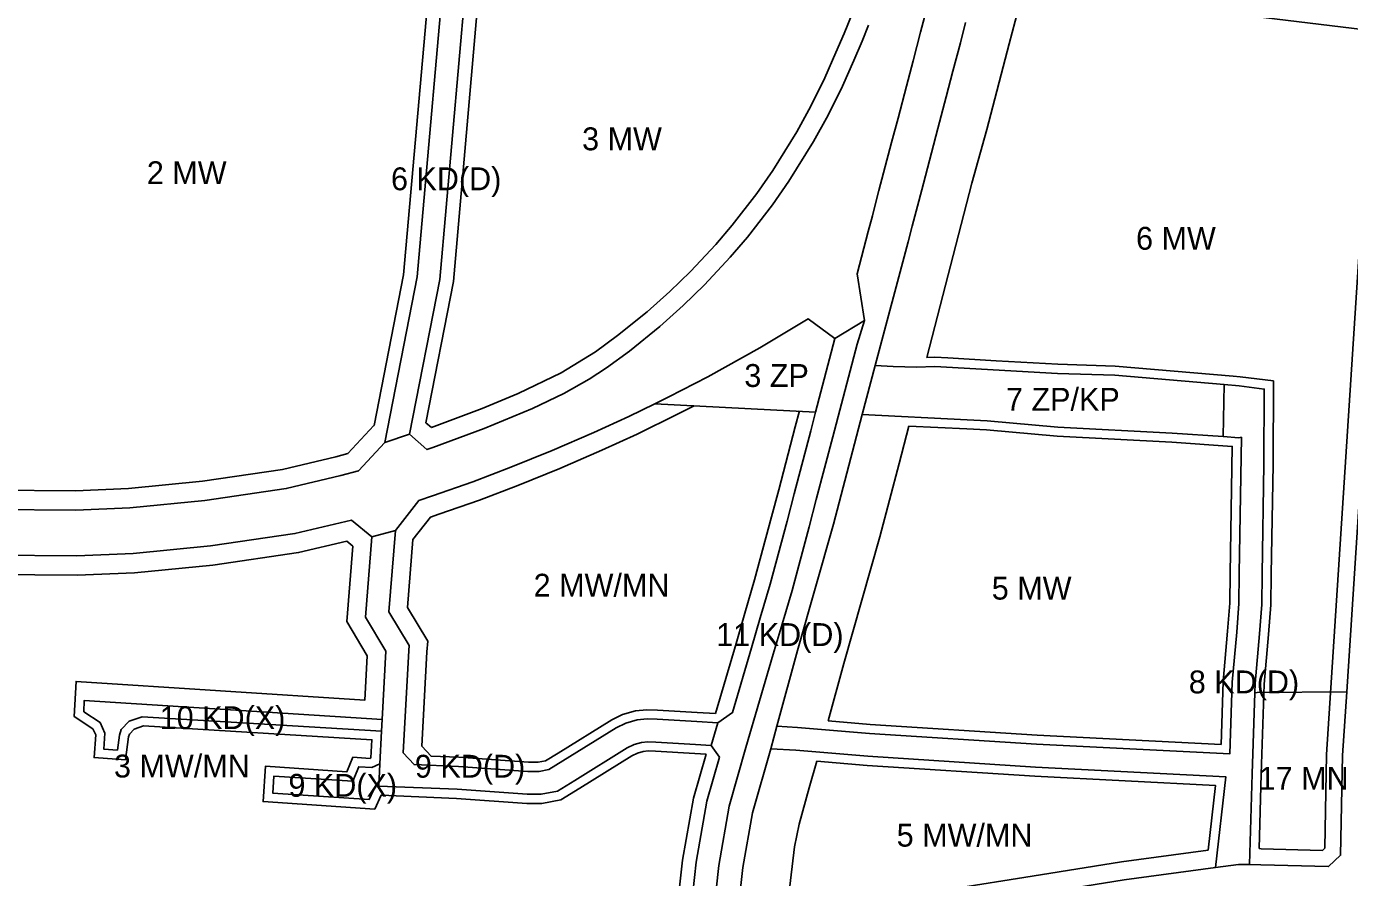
# Model space of a CAD drawing. Extents: x 7424258 to 7426021, y 5551671 to 5553193.
# Drawn here: x 7425011 to 7425590, y 5551891 to 5552263 of the extents above; entities that cross this region are included whole.
import ezdxf

# ---------------------------------------------------------------- set-up
doc = ezdxf.new("R2010")
doc.units = 0
for name, color, linetype in [('linie_rozgraniczajace', 7, 'Continuous'), ('linie_zabudowy_nieprzekraczalne', 7, 'Continuous'), ('oznaczenia_przeznaczen', 7, 'Continuous')]:
    doc.layers.add(name, color=color, linetype=linetype)

msp = doc.modelspace()

# ---------------------------------------------------------------- linework, layer by layer
at = {"layer": 'linie_rozgraniczajace'}
for points in [[(7424997.27, 5552325.91), (7425012.96, 5552360.1), (7425019.81, 5552362.55), (7425024.68, 5552360.58), (7425067.84, 5552343.87), (7425123.64, 5552327.99), (7425149.52, 5552322.73), (7425176.9, 5552317.94), (7425191.14, 5552316.45), (7425195.65, 5552310.79), (7425181.78, 5552153.52), (7425167.65, 5552081.05), (7425156.08, 5552068.62), (7425148.38, 5552066.54), (7425124.54, 5552060.86), (7425088.94, 5552055.71), (7425056.14, 5552052.4), (7425032.48, 5552051.43), (7424996.02, 5552051.74)], [(7425379.37, 5552263.62), (7425376.51, 5552256.56), (7425372.87, 5552248.13), (7425367.91, 5552236.88), (7425361.63, 5552224.15), (7425355.3, 5552212.64), (7425344.54, 5552195.31), (7425337.27, 5552184.92), (7425326.31, 5552170.76), (7425318.86, 5552162.02), (7425307.54, 5552149.92), (7425298.23, 5552140.87), (7425287.97, 5552131.72), (7425274.71, 5552121.02), (7425264.69, 5552113.7), (7425257.13, 5552108.73), (7425245.98, 5552102.38), (7425232.26, 5552095.88), (7425211.16, 5552087.11), (7425188.68, 5552078.8), (7425186.11, 5552077.95), (7425178.53, 5552084.62), (7425191.71, 5552152.38), (7425205.62, 5552309.91)], [(7425404.45, 5552269.24), (7425402.13, 5552260.45), (7425398.85, 5552247.95), (7425395.93, 5552236.83), (7425392.27, 5552222.89), (7425389.47, 5552212.23), (7425385.96, 5552198.95), (7425383.93, 5552191.17), (7425382.76, 5552186.71), (7425381.04, 5552180.19), (7425379.23, 5552173.31), (7425374.35, 5552154.75), (7425377.61, 5552134.39), (7425364.66, 5552126.55), (7425352.92, 5552135.1), (7425350.78, 5552133.84), (7425331.76, 5552122.47), (7425309.05, 5552109.69), (7425292.01, 5552100.99), (7425285.84, 5552097.94), (7425274.48, 5552092.35), (7425259.12, 5552085.41)], [(7425310.41, 5551865.34), (7425313.81, 5551896), (7425318.39, 5551921.94), (7425325.72, 5551947.69), (7425337.66, 5551988.37), (7425341.53, 5552001.56), (7425345.87, 5552016.33), (7425353.33, 5552044.09), (7425356.47, 5552056.06), (7425363.7, 5552083.52), (7425374.33, 5552124.01), (7425377.61, 5552134.39), (7425374.35, 5552154.75), (7425379.23, 5552173.31), (7425381.04, 5552180.19), (7425382.76, 5552186.71), (7425383.93, 5552191.17), (7425385.96, 5552198.95), (7425389.47, 5552212.23), (7425392.27, 5552222.89), (7425395.93, 5552236.83), (7425398.85, 5552247.95), (7425402.13, 5552260.45), (7425404.45, 5552269.24)], [(7424996.02, 5552051.74), (7425032.48, 5552051.43), (7425056.14, 5552052.4), (7425088.94, 5552055.71), (7425124.54, 5552060.86), (7425148.38, 5552066.54), (7425156.08, 5552068.62), (7425167.65, 5552081.05), (7425178.53, 5552084.62), (7425186.11, 5552077.95), (7425188.68, 5552078.8), (7425211.16, 5552087.11), (7425232.26, 5552095.88), (7425245.98, 5552102.38), (7425257.13, 5552108.73), (7425264.69, 5552113.7), (7425274.71, 5552121.02), (7425287.97, 5552131.72), (7425298.23, 5552140.87), (7425307.54, 5552149.92), (7425318.86, 5552162.02), (7425326.31, 5552170.76), (7425337.27, 5552184.92), (7425344.54, 5552195.31), (7425355.3, 5552212.64), (7425361.63, 5552224.15), (7425367.91, 5552236.88), (7425372.87, 5552248.13), (7425376.51, 5552256.56), (7425379.37, 5552263.62)], [(7425421.85, 5552264.67), (7425419.54, 5552255.88), (7425416.26, 5552243.37), (7425413.33, 5552232.27), (7425409.68, 5552218.34), (7425406.88, 5552207.65), (7425403.37, 5552194.36), (7425401.34, 5552186.6), (7425400.16, 5552182.14), (7425398.44, 5552175.61), (7425396.64, 5552168.73), (7425382.23, 5552114.68), (7425376.58, 5552093.23), (7425363.97, 5552045.24), (7425348.26, 5551989.98), (7425339.27, 5551956.93), (7425336.58, 5551947.06), (7425328.59, 5551919.07), (7425324.39, 5551895.19), (7425320.85, 5551863.31), (7425320.24, 5551863.23), (7425309.95, 5551861.15), (7425310.41, 5551865.34)], [(7425607.51, 5552262.2), (7425588.61, 5551971.9), (7425549.49, 5551971.62), (7425548.39, 5551971.53), (7425548.52, 5551975.6), (7425550.44, 5551997.31), (7425551.41, 5552010.12), (7425551.58, 5552023.54), (7425552.36, 5552071.42), (7425552.52, 5552104.4), (7425541.56, 5552105.82), (7425534.93, 5552106.38), (7425487.07, 5552110.47), (7425462.01, 5552111.26), (7425408.31, 5552114.33), (7425400.38, 5552113.93), (7425390.12, 5552114.25), (7425382.23, 5552114.68), (7425396.64, 5552168.73), (7425398.44, 5552175.61), (7425400.16, 5552182.14), (7425401.34, 5552186.6), (7425403.37, 5552194.36), (7425406.88, 5552207.65), (7425409.68, 5552218.34), (7425413.33, 5552232.27), (7425416.26, 5552243.37), (7425419.54, 5552255.88), (7425421.85, 5552264.67)], [(7425491.27, 5551889.67), (7425531.19, 5551895.08), (7425541.24, 5551896.43), (7425546.12, 5551896.39), (7425551.01, 5551896.36), (7425580.68, 5551895.56), (7425585.95, 5551900.49), (7425586.81, 5551944.16), (7425588.61, 5551971.9), (7425607.51, 5552262.2)], [(7425300.21, 5551864), (7425303.91, 5551897.42), (7425308.63, 5551924.18), (7425314.13, 5551943.45), (7425310.5, 5551948.55), (7425313.39, 5551958.39), (7425319.78, 5551962.92), (7425328.07, 5551991.18), (7425331.94, 5552004.37), (7425336.24, 5552019.04), (7425343.67, 5552046.66), (7425346.8, 5552058.59), (7425354.03, 5552086.06), (7425356.18, 5552094.28), (7425364.66, 5552126.55), (7425377.61, 5552134.39), (7425374.33, 5552124.01), (7425363.7, 5552083.52), (7425356.47, 5552056.06), (7425353.33, 5552044.09), (7425345.87, 5552016.33), (7425341.53, 5552001.56), (7425337.66, 5551988.37), (7425325.72, 5551947.69), (7425318.39, 5551921.94), (7425313.81, 5551896), (7425310.41, 5551865.34)], [(7425259.12, 5552085.41), (7425240.92, 5552077.45), (7425222.83, 5552070.18), (7425206.17, 5552063.81), (7425188.53, 5552057.68), (7425182.56, 5552055.69), (7425172.27, 5552042.59), (7425162.01, 5552039.75), (7425153.15, 5552047.11), (7425128.3, 5552041.2), (7425091.38, 5552035.86), (7425057.55, 5552032.45), (7425032.81, 5552031.43), (7424995.89, 5552031.74)], [(7424995.89, 5552031.74), (7425032.81, 5552031.43), (7425057.55, 5552032.45), (7425091.38, 5552035.86), (7425128.3, 5552041.2), (7425153.15, 5552047.11), (7425162.01, 5552039.75), (7425159.22, 5552004.59), (7425168.1, 5551989.8), (7425166.49, 5551959.88), (7425036.13, 5551968.24), (7425035.88, 5551963.25), (7425043.08, 5551958.49), (7425045.19, 5551953.93), (7425044.69, 5551946.94), (7425050.67, 5551946.51), (7425051.6, 5551953.07), (7425052.32, 5551955.53), (7425055.76, 5551959.08), (7425061.41, 5551961.09), (7425166.24, 5551954.79), (7425165.48, 5551940.52), (7425162.02, 5551938.82), (7425156.28, 5551939.19), (7425153.62, 5551932.84), (7425119.13, 5551935.13), (7425118.63, 5551927.65), (7425160.77, 5551924.81), (7425163.51, 5551930.86), (7425164.97, 5551930.75), (7425199.3, 5551929.35), (7425229.93, 5551927.18), (7425236.07, 5551927.14), (7425243.17, 5551928.5), (7425250.84, 5551933.23), (7425273.78, 5551947.42), (7425276.85, 5551948.95), (7425279.93, 5551949.84), (7425282.73, 5551950.09), (7425286.33, 5551949.98), (7425303.58, 5551948.94), (7425310.5, 5551948.55), (7425314.13, 5551943.45), (7425308.63, 5551924.18), (7425303.91, 5551897.42), (7425300.21, 5551864)]]:
    msp.add_lwpolyline(points, dxfattribs=at)
for points in [[(7425167.65, 5552081.05), (7425181.78, 5552153.52), (7425195.65, 5552310.79), (7425205.62, 5552309.91), (7425191.71, 5552152.38), (7425178.53, 5552084.62)], [(7425285.84, 5552097.94), (7425292.01, 5552100.99), (7425309.05, 5552109.69), (7425331.76, 5552122.47), (7425350.78, 5552133.84), (7425352.92, 5552135.1), (7425364.66, 5552126.55), (7425356.18, 5552094.28)], [(7425376.58, 5552093.23), (7425382.23, 5552114.68), (7425390.12, 5552114.25), (7425400.38, 5552113.93), (7425408.31, 5552114.33), (7425462.01, 5552111.26), (7425487.07, 5552110.47), (7425534.93, 5552106.38), (7425534.55, 5552083.59), (7425512.27, 5552085.09), (7425462.15, 5552087.72), (7425431.2, 5552090.54), (7425422.51, 5552090.96)], [(7425336.58, 5551947.06), (7425339.27, 5551956.93), (7425348.29, 5551956.43), (7425379.75, 5551953.75), (7425452.93, 5551949.03), (7425537.46, 5551944.78), (7425538.54, 5551976.22), (7425540.47, 5551998.13), (7425541.41, 5552010.57), (7425541.59, 5552023.69), (7425542.55, 5552083.28), (7425541.46, 5552083.12), (7425534.55, 5552083.59), (7425534.93, 5552106.38), (7425541.56, 5552105.82), (7425552.52, 5552104.4), (7425552.36, 5552071.42), (7425551.58, 5552023.54), (7425551.41, 5552010.12), (7425550.44, 5551997.31), (7425548.52, 5551975.6), (7425548.39, 5551971.53), (7425547.17, 5551936.1), (7425546.12, 5551896.39), (7425541.24, 5551896.43), (7425531.19, 5551895.08), (7425535.65, 5551934.86), (7425452.35, 5551939.05), (7425379, 5551943.78), (7425347.58, 5551946.45)], [(7425172.27, 5552042.59), (7425182.56, 5552055.69), (7425188.53, 5552057.68), (7425206.17, 5552063.81), (7425222.83, 5552070.18), (7425240.92, 5552077.45), (7425259.12, 5552085.41), (7425274.48, 5552092.35), (7425285.84, 5552097.94), (7425356.18, 5552094.28), (7425354.03, 5552086.06), (7425346.8, 5552058.59), (7425343.67, 5552046.66), (7425336.24, 5552019.04), (7425331.94, 5552004.37), (7425328.07, 5551991.18), (7425319.78, 5551962.92), (7425313.39, 5551958.39), (7425304.16, 5551958.92), (7425286.8, 5551959.97), (7425282.45, 5551960.11), (7425278.08, 5551959.71), (7425273.2, 5551958.3), (7425268.91, 5551956.16), (7425245.58, 5551941.74), (7425239.49, 5551937.98), (7425235.14, 5551937.14), (7425230.32, 5551937.17), (7425199.86, 5551939.34), (7425180.49, 5551940.13), (7425175.75, 5551945.32), (7425178.12, 5551989.98), (7425178.29, 5551992.23), (7425169.44, 5552006.99)], [(7425339.27, 5551956.93), (7425348.26, 5551989.98), (7425363.97, 5552045.24), (7425376.58, 5552093.23), (7425422.51, 5552090.96), (7425431.2, 5552090.54), (7425462.15, 5552087.72), (7425512.27, 5552085.09), (7425534.55, 5552083.59), (7425541.46, 5552083.12), (7425542.55, 5552083.28), (7425541.59, 5552023.69), (7425541.41, 5552010.57), (7425540.47, 5551998.13), (7425538.54, 5551976.22), (7425537.46, 5551944.78), (7425452.93, 5551949.03), (7425379.75, 5551953.75), (7425348.29, 5551956.43)], [(7425164.97, 5551930.75), (7425165.48, 5551940.52), (7425166.24, 5551954.79), (7425166.49, 5551959.88), (7425168.1, 5551989.8), (7425159.22, 5552004.59), (7425162.01, 5552039.75), (7425172.27, 5552042.59), (7425169.44, 5552006.99), (7425178.29, 5551992.23), (7425178.12, 5551989.98), (7425175.75, 5551945.32), (7425180.49, 5551940.13), (7425199.86, 5551939.34), (7425230.32, 5551937.17), (7425235.14, 5551937.14), (7425239.49, 5551937.98), (7425245.58, 5551941.74), (7425268.91, 5551956.16), (7425273.2, 5551958.3), (7425278.08, 5551959.71), (7425282.45, 5551960.11), (7425286.8, 5551959.97), (7425304.16, 5551958.92), (7425313.39, 5551958.39), (7425310.5, 5551948.55), (7425303.58, 5551948.94), (7425286.33, 5551949.98), (7425282.73, 5551950.09), (7425279.93, 5551949.84), (7425276.85, 5551948.95), (7425273.78, 5551947.42), (7425250.84, 5551933.23), (7425243.17, 5551928.5), (7425236.07, 5551927.14), (7425229.93, 5551927.18), (7425199.3, 5551929.35)], [(7425546.12, 5551896.39), (7425547.17, 5551936.1), (7425548.39, 5551971.53), (7425549.49, 5551971.62), (7425588.61, 5551971.9), (7425586.81, 5551944.16), (7425585.95, 5551900.49), (7425580.68, 5551895.56), (7425551.01, 5551896.36)], [(7425166.24, 5551954.79), (7425061.41, 5551961.09), (7425055.76, 5551959.08), (7425052.32, 5551955.53), (7425051.6, 5551953.07), (7425050.67, 5551946.51), (7425044.69, 5551946.94), (7425045.19, 5551953.93), (7425043.08, 5551958.49), (7425035.88, 5551963.25), (7425036.13, 5551968.24), (7425166.49, 5551959.88)], [(7425320.85, 5551863.31), (7425324.39, 5551895.19), (7425328.59, 5551919.07), (7425336.58, 5551947.06), (7425347.58, 5551946.45), (7425379, 5551943.78), (7425452.35, 5551939.05), (7425535.65, 5551934.86), (7425531.19, 5551895.08), (7425491.27, 5551889.67), (7425452.25, 5551883.42), (7425417.17, 5551877.82), (7425339.34, 5551866.07)], [(7425164.97, 5551930.75), (7425163.51, 5551930.86), (7425160.77, 5551924.81), (7425118.63, 5551927.65), (7425119.13, 5551935.13), (7425153.62, 5551932.84), (7425156.28, 5551939.19), (7425162.02, 5551938.82), (7425165.48, 5551940.52)]]:
    msp.add_lwpolyline(points, close=True, dxfattribs=at)
at = {"layer": 'linie_zabudowy_nieprzekraczalne'}
for points in [[(7425003.72, 5552323.19), (7425018.64, 5552355.47), (7425018.64, 5552355.47), (7425065.41, 5552337.31), (7425122.17, 5552321.15), (7425148.25, 5552315.85), (7425176.1, 5552310.98), (7425187.49, 5552309.79), (7425189.34, 5552307.48), (7425175.83, 5552154.35), (7425162.98, 5552088.46), (7425162.92, 5552088.44), (7425151.52, 5552076.19), (7425146.25, 5552074.77), (7425122.95, 5552069.22), (7425087.91, 5552064.15), (7425055.54, 5552060.89), (7425032.35, 5552059.93), (7424996.07, 5552060.24)], [(7425376.93, 5552290.95), (7425293.8, 5552298.69), (7425213.21, 5552307.11), (7425213.21, 5552307.11), (7425211.2, 5552305.45), (7425197.65, 5552151.43), (7425185.63, 5552089.69), (7425188.03, 5552087.58)], [(7425188.03, 5552087.58), (7425210.25, 5552095.93), (7425226.02, 5552102.49), (7425244.84, 5552111.51), (7425259.84, 5552120.68), (7425269.53, 5552127.76), (7425282.47, 5552138.2), (7425292.44, 5552147.09), (7425301.47, 5552155.87), (7425312.51, 5552167.69), (7425319.72, 5552176.13), (7425330.43, 5552189.95), (7425337.44, 5552199.99), (7425347.97, 5552216.93), (7425354.1, 5552228.08), (7425360.21, 5552240.47), (7425365.08, 5552251.53), (7425368.67, 5552259.84), (7425374.02, 5552273.24), (7425376.18, 5552279.35), (7425378.55, 5552285.86), (7425375, 5552291.13), (7425375, 5552291.13)], [(7425447.48, 5552280.34), (7425440.92, 5552255.39), (7425431.06, 5552217.89), (7425424.52, 5552194.47), (7425404.81, 5552118.16)], [(7425447.48, 5552280.34), (7425458.26, 5552278.45), (7425600.41, 5552261.05)], [(7425600.41, 5552261.05), (7425579.82, 5551944.61), (7425579, 5551903.58), (7425578, 5551902.64), (7425551.12, 5551903.36), (7425550.31, 5551903.38)], [(7425404.81, 5552118.16), (7425408.32, 5552118.34), (7425414.12, 5552118.01), (7425435.25, 5552116.79), (7425462.18, 5552115.25), (7425487.3, 5552114.47), (7425538.99, 5552110.05), (7425541.99, 5552109.8), (7425556.52, 5552107.92), (7425556.36, 5552071.35), (7425555.58, 5552023.48), (7425555.4, 5552009.95), (7425554.43, 5551996.99), (7425552.52, 5551975.36), (7425551.17, 5551935.98), (7425550.31, 5551903.38)], [(7425312.36, 5551962.46), (7425304.39, 5551962.91), (7425286.98, 5551963.96), (7425282.33, 5551964.11), (7425277.34, 5551963.66), (7425271.74, 5551962.05), (7425266.95, 5551959.66), (7425243.49, 5551945.14), (7425238.02, 5551941.77), (7425234.77, 5551941.15), (7425230.47, 5551941.17), (7425200.08, 5551943.33), (7425187.93, 5551943.82), (7425183.92, 5551948.24), (7425186.1, 5551989.5), (7425186.47, 5551994.16), (7425177.61, 5552008.91), (7425179.98, 5552038.65), (7425187.65, 5552048.43), (7425191.26, 5552049.62), (7425209.09, 5552055.82), (7425225.93, 5552062.26), (7425244.2, 5552069.6), (7425262.58, 5552077.64), (7425278.11, 5552084.67), (7425295.82, 5552093.39), (7425302.99, 5552097.05)], [(7425349.1, 5552094.85), (7425347.25, 5552087.84), (7425340.04, 5552060.38), (7425336.9, 5552048.45), (7425329.5, 5552020.93), (7425325.22, 5552006.34), (7425321.35, 5551993.15), (7425312.36, 5551962.46)], [(7425396.98, 5552088.22), (7425392.69, 5552071.89), (7425384.23, 5552039.7), (7425368.49, 5551984.35), (7425361.67, 5551959.3)], [(7425396.98, 5552088.22), (7425422.31, 5552086.96), (7425430.93, 5552086.55), (7425461.86, 5552083.73), (7425512.03, 5552081.1), (7425538.49, 5552079.31), (7425537.58, 5552023.75), (7425537.41, 5552010.74), (7425536.49, 5551998.45), (7425534.54, 5551976.46), (7425533.61, 5551948.98), (7425453.16, 5551953.02), (7425380.05, 5551957.74), (7425361.67, 5551959.3)], [(7424973.91, 5552023.34), (7424995.83, 5552023.24), (7425032.95, 5552022.93), (7425058.16, 5552023.96), (7425092.42, 5552027.42), (7425129.9, 5552032.84), (7425150.98, 5552037.86)], [(7425308.23, 5551944.67), (7425303.34, 5551944.94), (7425286.15, 5551945.98), (7425282.85, 5551946.09), (7425280.67, 5551945.89), (7425278.31, 5551945.21), (7425275.73, 5551943.92), (7425252.94, 5551929.82), (7425244.65, 5551924.72), (7425236.43, 5551923.14), (7425229.78, 5551923.18), (7425199.08, 5551925.35), (7425166.02, 5551926.71), (7425163.28, 5551920.63), (7425114.37, 5551923.93), (7425115.41, 5551939.39), (7425151.04, 5551937.02), (7425153.69, 5551943.36), (7425161.21, 5551942.88), (7425161.61, 5551943.08), (7425162.04, 5551951.04), (7425061.98, 5551957.05), (7425057.98, 5551955.62), (7425055.88, 5551953.46), (7425055.52, 5551952.22), (7425054.11, 5551942.26), (7425040.42, 5551943.24), (7425041.12, 5551953.18), (7425039.92, 5551955.78), (7425031.77, 5551961.17), (7425032.53, 5551976.49), (7425158.95, 5551968.37), (7425159.98, 5551987.78), (7425151.04, 5552002.67), (7425153.66, 5552035.64), (7425150.98, 5552037.86)], [(7425286.01, 5551859.2), (7425294.49, 5551866.91), (7425294.49, 5551866.91), (7425297.96, 5551898.28), (7425302.78, 5551925.53), (7425308.23, 5551944.67)], [(7425356.74, 5551941.66), (7425353.44, 5551929.94), (7425348.99, 5551914.07), (7425346.91, 5551904.18), (7425343.38, 5551874.77)], [(7425356.74, 5551941.66), (7425378.71, 5551939.79), (7425452.13, 5551935.05), (7425531.19, 5551931.07), (7425528.02, 5551902.71)], [(7425528.02, 5551902.71), (7425490.1, 5551897.58), (7425450.99, 5551891.32), (7425416.06, 5551885.74), (7425343.38, 5551874.77)], [(7425550.12, 5551896.37), (7425550.12, 5551896.29)]]:
    msp.add_lwpolyline(points, dxfattribs=at)

# ---------------------------------------------------------------- texts
at = {"layer": 'oznaczenia_przeznaczen'}
for s, p in [('3 MW', (7425254, 5552208.83)), ('2 MW', (7425063.51, 5552194.01)), ('6 KD(D)', (7425170.36, 5552191.35)), ('6 MW', (7425496.42, 5552165.33)), ('3 ZP', (7425324.99, 5552105.31)), ('7 ZP/KP', (7425439.5, 5552094.91)), ('2 MW/MN', (7425232.79, 5552013.6)), ('5 MW', (7425433.28, 5552012.31)), ('11 KD(D)', (7425312.69, 5551992.01)), ('8 KD(D)', (7425519.51, 5551971.3)), ('10 KD(X)', (7425069.14, 5551955.64)), ('3 MW/MN', (7425049.14, 5551934.5)), ('9 KD(D)', (7425180.83, 5551934.42)), ('9 KD(X)', (7425125.47, 5551926.08)), ('17 MN', (7425550.08, 5551929.13)), ('5 MW/MN', (7425391.66, 5551904.27))]:
    msp.add_text(s, height=10, dxfattribs=at).set_placement(p)

doc.saveas('drawing.dxf')
